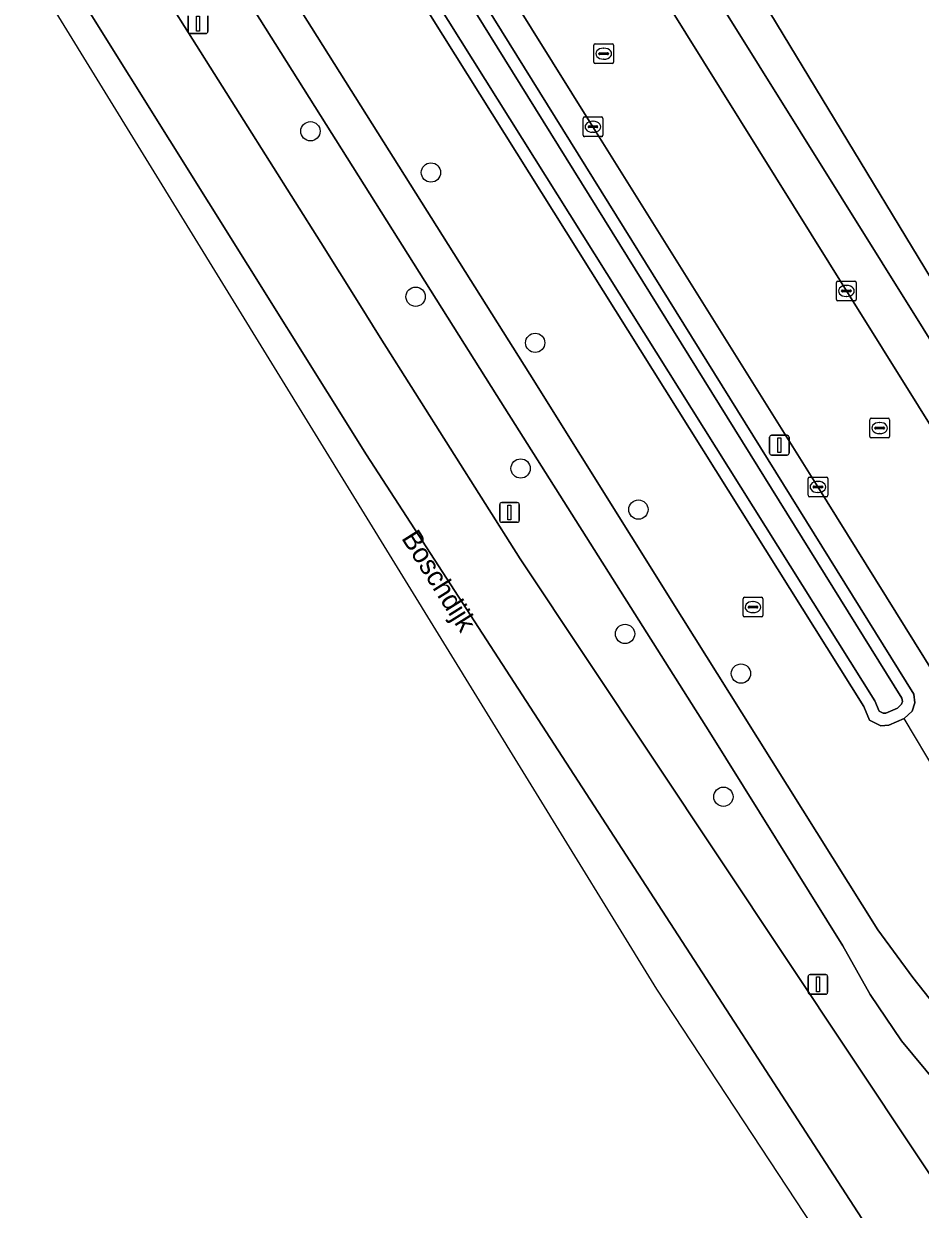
# Model space of a CAD drawing. Extents: x 158835 to 160077, y 386387 to 387778.
# Drawn here: x 159046.4 to 159091.8, y 386814 to 386874.1 of the extents above; entities that cross this region are included whole.
import ezdxf

# ---------------------------------------------------------------- set-up
doc = ezdxf.new("R2010")
doc.units = 0
for name, color, linetype in [('IMGEO_Berm_groen', 7, 'Continuous'), ('IMGEO_Boom', 7, 'Continuous'), ('IMGEO_Brandkraan', 7, 'Continuous'), ('IMGEO_Duiker', 7, 'Continuous'), ('IMGEO_Fietspad_gesloten', 7, 'Continuous'), ('IMGEO_Greppel_droge_sloot', 7, 'Continuous'), ('IMGEO_Kolk', 7, 'Continuous'), ('IMGEO_Lichtmast', 7, 'Continuous'), ('IMGEO_Loofbos', 7, 'Continuous'), ('IMGEO_Oever', 7, 'Continuous'), ('IMGEO_Openbare_ruimte_label', 7, 'Continuous'), ('IMGEO_Rijbaan_lokaal_open', 7, 'Continuous'), ('IMGEO_Rijbaan_regionaal_gesloten', 7, 'Continuous'), ('IMGEO_Rioolput', 7, 'Continuous'), ('IMGEO_Voetpad_open', 7, 'Continuous')]:
    doc.layers.add(name, color=color, linetype=linetype)

msp = doc.modelspace()

# ---------------------------------------------------------------- linework, layer by layer
at = {"layer": 'IMGEO_Berm_groen'}
for points in [[(159035.265, 386925.216), (159000, 386981.943), (158990.004, 386998.024), (158991.693, 386999.224), (159000, 386986.242), (159057.921, 386894.086), (159063.62, 386885.019), (159091.508, 386840.108), (159091.568, 386839.665), (159091.422, 386839.242), (159091.028, 386838.871), (159090.244, 386838.524), (159089.835, 386838.498), (159089.256, 386838.78), (159088.981, 386839.474), (159055.682, 386892.626)], [(159142.528, 386822.4), (159123.048, 386814.194), (159109.025, 386833.71), (159070.867, 386896.72), (159089.158, 386908.868)]]:
    msp.add_lwpolyline(points, close=True, dxfattribs=at)
for points in [[(159096.401, 386906.705), (159091.296, 386914.922), (159067.709, 386900.255), (159067.552, 386900.158), (159076.413, 386885.966), (159075.363, 386885.31), (159125.228, 386805.37)], [(159051.929, 386888.316), (159072.053, 386856.336), (159079.753, 386844.002), (159082.8, 386839.159), (159089.683, 386828.15), (159091.461, 386825.74), (159093.442, 386823.227), (159095.249, 386821.212), (159101.304, 386815.324), (159102.451, 386814.209), (159102.504, 386814.154), (159105.291, 386810.988), (159107.784, 386807.586), (159123.016, 386783.333), (159143.952, 386750)], [(159101.834, 386811.269), (159099.079, 386814.018), (159096.324, 386816.766), (159093.62, 386819.341), (159092.687, 386820.335), (159090.889, 386822.524), (159089.294, 386824.866), (159087.914, 386827.34), (159081.168, 386838.156), (159070.38, 386855.242), (159050.784, 386886.396)], [(159048.457, 386883.647), (159061.455, 386863.013), (159063.391, 386859.93), (159064.463, 386858.196), (159071.557, 386846.971), (159095.09, 386811.591)], [(159128.6, 386783.846), (159121.784, 386794.465), (159121.337, 386794.968), (159120.937, 386795.51), (159119.183, 386798.375), (159108.33, 386815.791), (159097.471, 386833.198), (159086.653, 386850.613), (159075.251, 386868.876), (159065.997, 386883.711)]]:
    msp.add_lwpolyline(points, dxfattribs=at)
at = {"layer": 'IMGEO_Boom'}
for centre in [(159060.934, 386868.651), (159067.04, 386866.557), (159066.264, 386860.259), (159072.323, 386857.92), (159071.586, 386851.549), (159077.553, 386849.464), (159076.875, 386843.159), (159082.751, 386841.147), (159081.861, 386834.9)]:
    msp.add_circle(centre, 0.489, dxfattribs=at)
at = {"layer": 'IMGEO_Brandkraan'}
for p, q in [((159082.859, 386844.091), (159082.859, 386844.943)), ((159082.934, 386845.017), (159083.786, 386845.017)), ((159083.118, 386844.511), (159083.118, 386844.523)), ((159083.556, 386844.474), (159083.158, 386844.474)), ((159083.161, 386844.56), (159083.559, 386844.56)), ((159083.347, 386844.797), (159083.372, 386844.797)), ((159083.602, 386844.523), (159083.602, 386844.511)), ((159083.86, 386844.943), (159083.86, 386844.091)), ((159083.786, 386844.017), (159082.934, 386844.017)), ((159083.37, 386844.237), (159083.345, 386844.237))]:
    msp.add_line(p, q, dxfattribs=at)
for points in [[(159082.859, 386844.091), (159082.859, 386844.943)], [(159082.934, 386845.017), (159083.786, 386845.017)], [(159083.86, 386844.943), (159083.86, 386844.091)], [(159083.786, 386844.017), (159082.934, 386844.017)]]:
    msp.add_lwpolyline(points, dxfattribs=at)
for centre, radius, start, end in [((159082.936, 386844.941), 0.0765, 91.55205, 178.44795), ((159082.936, 386844.941), 0.0765, 91.55205, 178.44795), ((159083.158, 386844.52), 0.0403, 85.87752, 175.75265), ((159083.155, 386844.51), 0.0366, 178.93798, 274.71019), ((159083.559, 386844.517), 0.043, 264.86636, 352.45326), ((159083.563, 386844.522), 0.0386, 1.73085, 96.63898), ((159083.784, 386844.941), 0.0765, 1.55205, 88.44795), ((159083.784, 386844.941), 0.0765, 1.55205, 88.44795), ((159082.936, 386844.093), 0.0765, 181.55205, 268.44795), ((159082.936, 386844.093), 0.0765, 181.55205, 268.44795), ((159083.784, 386844.093), 0.0765, 271.55205, 358.44795), ((159083.784, 386844.093), 0.0765, 271.55205, 358.44795)]:
    msp.add_arc(centre, radius, start, end, dxfattribs=at)
for centre, major_axis, ratio, start_param, end_param in [((159083.346, 386844.517), (-0.387, 0.002), 0.722429, 4.712389, 7.853982), ((159083.371, 386844.517), (-0.39, 0.002), 0.717154, 1.570796, 4.712389)]:
    msp.add_ellipse(centre, major_axis=major_axis, ratio=ratio, start_param=start_param, end_param=end_param, dxfattribs=at)
at = {"layer": 'IMGEO_Duiker'}
msp.add_lwpolyline([(159092.842, 386835.807), (159092.695, 386836.055), (159091.028, 386838.871)], dxfattribs=at)
at = {"layer": 'IMGEO_Fietspad_gesloten'}
for points in [[(159143.952, 386750), (159123.016, 386783.333), (159107.784, 386807.586), (159105.291, 386810.988), (159102.504, 386814.154), (159102.451, 386814.209), (159101.304, 386815.324), (159095.249, 386821.212), (159093.442, 386823.227), (159091.461, 386825.74), (159089.683, 386828.15), (159082.8, 386839.159), (159079.753, 386844.002), (159072.053, 386856.336), (159051.929, 386888.316)], [(159050.784, 386886.396), (159070.38, 386855.242), (159081.168, 386838.156), (159087.914, 386827.34), (159089.294, 386824.866), (159090.889, 386822.524), (159092.687, 386820.335), (159093.62, 386819.341), (159096.324, 386816.766), (159099.079, 386814.018), (159101.834, 386811.269), (159102.217, 386810.854), (159103.824, 386808.91), (159105.251, 386806.829), (159117.605, 386787.425), (159119.088, 386785.097), (159120.445, 386782.966), (159121.265, 386781.617), (159125.349, 386775.064), (159128.77, 386769.613)]]:
    msp.add_lwpolyline(points, dxfattribs=at)
at = {"layer": 'IMGEO_Greppel_droge_sloot'}
msp.add_lwpolyline([(158999.473, 386985.908), (158991.52, 386998.336), (158991.091, 386998.031), (158990.844, 386997.855), (159000.53, 386982.272), (159035.794, 386925.546), (159056.211, 386892.957), (159089.54, 386839.757), (159089.747, 386839.235), (159089.96, 386839.131), (159090.093, 386839.14), (159090.678, 386839.399), (159090.882, 386839.591), (159090.93, 386839.728), (159090.907, 386839.892), (159063.091, 386884.688), (159057.393, 386893.754)], close=True, dxfattribs=at)
at = {"layer": 'IMGEO_Kolk'}
for p, q in [((159074.749, 386868.45), (159074.749, 386869.302)), ((159074.824, 386869.376), (159075.676, 386869.376)), ((159075.237, 386869.156), (159075.262, 386869.156)), ((159075.75, 386869.302), (159075.75, 386868.45)), ((159075.008, 386868.87), (159075.008, 386868.882)), ((159075.446, 386868.833), (159075.048, 386868.833)), ((159075.051, 386868.919), (159075.449, 386868.919)), ((159075.26, 386868.596), (159075.235, 386868.596)), ((159075.492, 386868.882), (159075.492, 386868.87)), ((159075.676, 386868.376), (159074.824, 386868.376)), ((159087.592, 386860.125), (159087.592, 386860.977)), ((159087.667, 386861.051), (159088.519, 386861.051)), ((159088.08, 386860.831), (159088.105, 386860.831)), ((159088.593, 386860.977), (159088.593, 386860.125)), ((159087.851, 386860.545), (159087.851, 386860.557)), ((159088.289, 386860.508), (159087.891, 386860.508)), ((159087.894, 386860.594), (159088.292, 386860.594)), ((159088.103, 386860.271), (159088.078, 386860.271)), ((159088.335, 386860.557), (159088.335, 386860.545)), ((159088.519, 386860.051), (159087.667, 386860.051)), ((159086.225, 386851.113), (159087.077, 386851.113)), ((159086.15, 386850.187), (159086.15, 386851.039)), ((159086.409, 386850.607), (159086.409, 386850.619)), ((159086.847, 386850.57), (159086.449, 386850.57)), ((159086.452, 386850.656), (159086.85, 386850.656)), ((159086.638, 386850.893), (159086.663, 386850.893)), ((159086.893, 386850.619), (159086.893, 386850.607)), ((159087.151, 386851.039), (159087.151, 386850.187)), ((159087.077, 386850.113), (159086.225, 386850.113)), ((159086.661, 386850.333), (159086.636, 386850.333))]:
    msp.add_line(p, q, dxfattribs=at)
for points in [[(159074.749, 386868.45), (159074.749, 386869.302)], [(159074.824, 386869.376), (159075.676, 386869.376)], [(159075.75, 386869.302), (159075.75, 386868.45)], [(159075.676, 386868.376), (159074.824, 386868.376)], [(159087.592, 386860.125), (159087.592, 386860.977)], [(159087.667, 386861.051), (159088.519, 386861.051)], [(159088.593, 386860.977), (159088.593, 386860.125)], [(159088.519, 386860.051), (159087.667, 386860.051)], [(159086.225, 386851.113), (159087.077, 386851.113)], [(159086.15, 386850.187), (159086.15, 386851.039)], [(159087.151, 386851.039), (159087.151, 386850.187)], [(159087.077, 386850.113), (159086.225, 386850.113)]]:
    msp.add_lwpolyline(points, dxfattribs=at)
for centre, radius, start, end in [((159074.826, 386869.3), 0.0765, 91.55205, 178.44795), ((159074.826, 386869.3), 0.0765, 91.55205, 178.44795), ((159075.674, 386869.3), 0.0765, 1.55205, 88.44795), ((159075.674, 386869.3), 0.0765, 1.55205, 88.44795), ((159075.048, 386868.879), 0.0403, 85.87752, 175.75265), ((159075.045, 386868.869), 0.0366, 178.93798, 274.71019), ((159075.449, 386868.876), 0.043, 264.86636, 352.45326), ((159075.453, 386868.881), 0.0386, 1.73085, 96.63898), ((159074.826, 386868.452), 0.0765, 181.55205, 268.44795), ((159074.826, 386868.452), 0.0765, 181.55205, 268.44795), ((159075.674, 386868.452), 0.0765, 271.55205, 358.44795), ((159075.674, 386868.452), 0.0765, 271.55205, 358.44795), ((159087.669, 386860.975), 0.0765, 91.55205, 178.44795), ((159087.669, 386860.975), 0.0765, 91.55205, 178.44795), ((159088.517, 386860.975), 0.0765, 1.55205, 88.44795), ((159088.517, 386860.975), 0.0765, 1.55205, 88.44795), ((159087.669, 386860.127), 0.0765, 181.55205, 268.44795), ((159087.669, 386860.127), 0.0765, 181.55205, 268.44795), ((159087.891, 386860.554), 0.0403, 85.87752, 175.75265), ((159087.888, 386860.544), 0.0366, 178.93798, 274.71019), ((159088.292, 386860.551), 0.043, 264.86636, 352.45326), ((159088.296, 386860.556), 0.0386, 1.73085, 96.63898), ((159088.517, 386860.127), 0.0765, 271.55205, 358.44795), ((159088.517, 386860.127), 0.0765, 271.55205, 358.44795), ((159086.227, 386851.037), 0.0765, 91.55205, 178.44795), ((159086.227, 386851.037), 0.0765, 91.55205, 178.44795), ((159087.075, 386851.037), 0.0765, 1.55205, 88.44795), ((159087.075, 386851.037), 0.0765, 1.55205, 88.44795), ((159086.449, 386850.616), 0.0403, 85.87752, 175.75265), ((159086.446, 386850.606), 0.0366, 178.93798, 274.71019), ((159086.85, 386850.613), 0.043, 264.86636, 352.45326), ((159086.854, 386850.618), 0.0386, 1.73085, 96.63898), ((159086.227, 386850.189), 0.0765, 181.55205, 268.44795), ((159086.227, 386850.189), 0.0765, 181.55205, 268.44795), ((159087.075, 386850.189), 0.0765, 271.55205, 358.44795), ((159087.075, 386850.189), 0.0765, 271.55205, 358.44795)]:
    msp.add_arc(centre, radius, start, end, dxfattribs=at)
for centre, major_axis, ratio, start_param, end_param in [((159075.236, 386868.876), (-0.387, 0.002), 0.722429, 4.712389, 7.853982), ((159075.261, 386868.876), (-0.39, 0.002), 0.717154, 1.570796, 4.712389), ((159088.079, 386860.551), (-0.387, 0.002), 0.722429, 4.712389, 7.853982), ((159088.104, 386860.551), (-0.39, 0.002), 0.717154, 1.570796, 4.712389), ((159086.637, 386850.613), (-0.387, 0.002), 0.722429, 4.712389, 7.853982), ((159086.662, 386850.613), (-0.39, 0.002), 0.717154, 1.570796, 4.712389)]:
    msp.add_ellipse(centre, major_axis=major_axis, ratio=ratio, start_param=start_param, end_param=end_param, dxfattribs=at)
at = {"layer": 'IMGEO_Lichtmast'}
for p, q in [((159054.746, 386873.707), (159054.746, 386874.507)), ((159054.746, 386874.507), (159054.746, 386873.707)), ((159055.736, 386874.507), (159055.736, 386873.707)), ((159055.736, 386873.707), (159055.736, 386874.507)), ((159055.636, 386873.607), (159054.846, 386873.607)), ((159054.846, 386873.607), (159055.636, 386873.607)), ((159084.198, 386852.331), (159084.198, 386853.131)), ((159084.198, 386853.131), (159084.198, 386852.331)), ((159084.298, 386853.231), (159085.088, 386853.231)), ((159085.088, 386853.231), (159084.298, 386853.231)), ((159085.188, 386853.131), (159085.188, 386852.331)), ((159085.188, 386852.331), (159085.188, 386853.131)), ((159085.088, 386852.231), (159084.298, 386852.231)), ((159084.298, 386852.231), (159085.088, 386852.231)), ((159070.525, 386848.918), (159070.525, 386849.718)), ((159070.525, 386849.718), (159070.525, 386848.918)), ((159070.625, 386849.818), (159071.415, 386849.818)), ((159071.415, 386849.818), (159070.625, 386849.818)), ((159071.515, 386849.718), (159071.515, 386848.918)), ((159071.515, 386848.918), (159071.515, 386849.718)), ((159071.415, 386848.818), (159070.625, 386848.818)), ((159070.625, 386848.818), (159071.415, 386848.818)), ((159086.253, 386825.885), (159087.043, 386825.885)), ((159087.043, 386825.885), (159086.253, 386825.885)), ((159086.153, 386824.985), (159086.153, 386825.785)), ((159086.153, 386825.785), (159086.153, 386824.985)), ((159087.143, 386825.785), (159087.143, 386824.985)), ((159087.143, 386824.985), (159087.143, 386825.785)), ((159087.043, 386824.885), (159086.253, 386824.885)), ((159086.253, 386824.885), (159087.043, 386824.885))]:
    msp.add_line(p, q, dxfattribs=at)
for points in [[(159055.166, 386874.482), (159055.316, 386874.482), (159055.316, 386873.732), (159055.166, 386873.732), (159055.166, 386874.482)], [(159084.618, 386853.106), (159084.768, 386853.106), (159084.768, 386852.356), (159084.618, 386852.356), (159084.618, 386853.106)], [(159070.945, 386849.693), (159071.095, 386849.693), (159071.095, 386848.943), (159070.945, 386848.943), (159070.945, 386849.693)], [(159086.573, 386825.76), (159086.723, 386825.76), (159086.723, 386825.01), (159086.573, 386825.01), (159086.573, 386825.76)]]:
    msp.add_lwpolyline(points, dxfattribs=at)
for centre, start, end in [((159054.846, 386873.707), 180, 270), ((159054.846, 386873.707), 180, 270), ((159055.636, 386873.707), 270, 0), ((159055.636, 386873.707), 270, 0), ((159084.298, 386853.131), 90, 180), ((159084.298, 386853.131), 90, 180), ((159085.088, 386853.131), 0, 90), ((159085.088, 386853.131), 360, 90), ((159084.298, 386852.331), 180, 270), ((159084.298, 386852.331), 180, 270), ((159085.088, 386852.331), 270, 0), ((159085.088, 386852.331), 270, 0), ((159070.625, 386849.718), 90, 180), ((159070.625, 386849.718), 90, 180), ((159071.415, 386849.718), 0, 90), ((159071.415, 386849.718), 360, 90), ((159070.625, 386848.918), 180, 270), ((159070.625, 386848.918), 180, 270), ((159071.415, 386848.918), 270, 0), ((159071.415, 386848.918), 270, 0), ((159086.253, 386825.785), 90, 180), ((159086.253, 386825.785), 90, 180), ((159087.043, 386825.785), 0, 90), ((159087.043, 386825.785), 360, 90), ((159086.253, 386824.985), 180, 270), ((159086.253, 386824.985), 180, 270), ((159087.043, 386824.985), 270, 0), ((159087.043, 386824.985), 270, 0)]:
    msp.add_arc(centre, 0.1, start, end, dxfattribs=at)
at = {"layer": 'IMGEO_Loofbos'}
msp.add_lwpolyline([(159123.048, 386814.194), (159142.528, 386822.4), (159089.158, 386908.868), (159070.867, 386896.72), (159109.025, 386833.71)], close=True, dxfattribs=at)
at = {"layer": 'IMGEO_Oever'}
for points in [[(159000, 386986.242), (158991.693, 386999.224), (158990.004, 386998.024), (159000, 386981.943), (159035.265, 386925.216), (159055.682, 386892.626), (159088.981, 386839.474), (159089.256, 386838.78), (159089.835, 386838.498), (159090.244, 386838.524), (159091.028, 386838.871), (159091.422, 386839.242), (159091.568, 386839.665), (159091.508, 386840.108), (159063.62, 386885.019), (159057.921, 386894.086)], [(158999.473, 386985.908), (159057.393, 386893.754), (159063.091, 386884.688), (159090.907, 386839.892), (159090.93, 386839.728), (159090.882, 386839.591), (159090.678, 386839.399), (159090.093, 386839.14), (159089.96, 386839.131), (159089.747, 386839.235), (159089.54, 386839.757), (159056.211, 386892.957), (159035.794, 386925.546), (159000.53, 386982.272), (158990.844, 386997.855), (158991.091, 386998.031), (158991.52, 386998.336)]]:
    msp.add_lwpolyline(points, close=True, dxfattribs=at)
at = {"layer": 'IMGEO_Rijbaan_lokaal_open'}
for points in [[(159065.997, 386883.711), (159075.251, 386868.876), (159086.653, 386850.613), (159097.471, 386833.198), (159108.33, 386815.791), (159119.183, 386798.375), (159120.937, 386795.51), (159121.337, 386794.968), (159121.784, 386794.465), (159122.274, 386794.003), (159122.804, 386793.587), (159123.173, 386793.339), (159124.451, 386792.618), (159125.788, 386792.014), (159127.174, 386791.531), (159128.597, 386791.175), (159129.11, 386791.079), (159129.323, 386791.054), (159129.442, 386791.04)], [(159123.327, 386804.096), (159120.096, 386809.226), (159109.823, 386825.714), (159098.952, 386843.149), (159088.091, 386860.551), (159077.264, 386877.959)]]:
    msp.add_lwpolyline(points, dxfattribs=at)
at = {"layer": 'IMGEO_Rijbaan_regionaal_gesloten'}
msp.add_lwpolyline([(158852.084, 387188.493), (158892.201, 387121.78), (158943.79, 387040.765), (159022.005, 386917.023), (159078.47, 386825.145), (159142.367, 386727.985), (159143.031, 386728.393), (159114.787, 386773.529), (159063.769, 386852.239), (159047.794, 386877.825), (159027.337, 386910.591), (159001.844, 386951.425), (158973.435, 386996.928), (158951.308, 387032.368), (158919.283, 387083.664), (158891.623, 387127.967), (158871.393, 387160.012), (158853.231, 387189.196)], close=True, dxfattribs=at)
msp.add_lwpolyline([(159047.794, 386877.825), (159063.769, 386852.239), (159114.787, 386773.529), (159143.031, 386728.393), (159146.173, 386730.325), (159146.161, 386730.344), (159145.513, 386731.372), (159137.834, 386743.694), (159134, 386749.851), (159098.75, 386806.078), (159095.71, 386810.659), (159095.09, 386811.591), (159071.557, 386846.971), (159064.463, 386858.196), (159063.391, 386859.93), (159061.455, 386863.013), (159048.457, 386883.647)], dxfattribs=at)
at = {"layer": 'IMGEO_Rioolput'}
for p, q in [((159075.294, 386872.158), (159075.294, 386873.01)), ((159075.369, 386873.084), (159076.221, 386873.084)), ((159075.782, 386872.864), (159075.807, 386872.864)), ((159076.295, 386873.01), (159076.295, 386872.158)), ((159075.553, 386872.578), (159075.553, 386872.59)), ((159075.991, 386872.541), (159075.593, 386872.541)), ((159075.596, 386872.627), (159075.994, 386872.627)), ((159075.805, 386872.304), (159075.78, 386872.304)), ((159076.037, 386872.59), (159076.037, 386872.578)), ((159076.221, 386872.084), (159075.369, 386872.084)), ((159089.353, 386854.097), (159090.205, 386854.097)), ((159089.278, 386853.171), (159089.278, 386854.023)), ((159089.537, 386853.591), (159089.537, 386853.603)), ((159089.975, 386853.554), (159089.577, 386853.554)), ((159089.58, 386853.64), (159089.978, 386853.64)), ((159089.766, 386853.877), (159089.791, 386853.877)), ((159090.021, 386853.603), (159090.021, 386853.591)), ((159090.279, 386854.023), (159090.279, 386853.171)), ((159090.205, 386853.097), (159089.353, 386853.097)), ((159089.789, 386853.317), (159089.764, 386853.317))]:
    msp.add_line(p, q, dxfattribs=at)
for points in [[(159075.294, 386872.158), (159075.294, 386873.01)], [(159075.369, 386873.084), (159076.221, 386873.084)], [(159076.295, 386873.01), (159076.295, 386872.158)], [(159076.221, 386872.084), (159075.369, 386872.084)], [(159089.353, 386854.097), (159090.205, 386854.097)], [(159089.278, 386853.171), (159089.278, 386854.023)], [(159090.279, 386854.023), (159090.279, 386853.171)], [(159090.205, 386853.097), (159089.353, 386853.097)]]:
    msp.add_lwpolyline(points, dxfattribs=at)
for centre, radius, start, end in [((159075.371, 386873.008), 0.0765, 91.55205, 178.44795), ((159075.371, 386873.008), 0.0765, 91.55205, 178.44795), ((159076.219, 386873.008), 0.0765, 1.55205, 88.44795), ((159076.219, 386873.008), 0.0765, 1.55205, 88.44795), ((159075.371, 386872.16), 0.0765, 181.55205, 268.44795), ((159075.371, 386872.16), 0.0765, 181.55205, 268.44795), ((159075.593, 386872.587), 0.0403, 85.87752, 175.75265), ((159075.59, 386872.577), 0.0366, 178.93798, 274.71019), ((159075.994, 386872.584), 0.043, 264.86636, 352.45326), ((159075.998, 386872.589), 0.0386, 1.73085, 96.63898), ((159076.219, 386872.16), 0.0765, 271.55205, 358.44795), ((159076.219, 386872.16), 0.0765, 271.55205, 358.44795), ((159089.355, 386854.021), 0.0765, 91.55205, 178.44795), ((159089.355, 386854.021), 0.0765, 91.55205, 178.44795), ((159090.203, 386854.021), 0.0765, 1.55205, 88.44795), ((159090.203, 386854.021), 0.0765, 1.55205, 88.44795), ((159089.577, 386853.6), 0.0403, 85.87752, 175.75265), ((159089.574, 386853.59), 0.0366, 178.93798, 274.71019), ((159089.978, 386853.597), 0.043, 264.86636, 352.45326), ((159089.982, 386853.602), 0.0386, 1.73085, 96.63898), ((159089.355, 386853.173), 0.0765, 181.55205, 268.44795), ((159089.355, 386853.173), 0.0765, 181.55205, 268.44795), ((159090.203, 386853.173), 0.0765, 271.55205, 358.44795), ((159090.203, 386853.173), 0.0765, 271.55205, 358.44795)]:
    msp.add_arc(centre, radius, start, end, dxfattribs=at)
for centre, major_axis, ratio, start_param, end_param in [((159075.781, 386872.584), (-0.387, 0.002), 0.722429, 4.712389, 7.853982), ((159075.806, 386872.584), (-0.39, 0.002), 0.717154, 1.570796, 4.712389), ((159089.765, 386853.597), (-0.387, 0.002), 0.722429, 4.712389, 7.853982), ((159089.79, 386853.597), (-0.39, 0.002), 0.717154, 1.570796, 4.712389)]:
    msp.add_ellipse(centre, major_axis=major_axis, ratio=ratio, start_param=start_param, end_param=end_param, dxfattribs=at)
at = {"layer": 'IMGEO_Voetpad_open'}
for points in [[(159125.228, 386805.37), (159075.363, 386885.31), (159076.413, 386885.966), (159067.552, 386900.158), (159066.88, 386899.741), (159066.666, 386899.609), (159066.583, 386899.738), (159064.514, 386898.388), (159065.265, 386897.218)], [(159073.44, 386884.112), (159077.264, 386877.959), (159088.091, 386860.551), (159098.952, 386843.149), (159109.823, 386825.714), (159120.096, 386809.226), (159123.327, 386804.096)]]:
    msp.add_lwpolyline(points, dxfattribs=at)

# ---------------------------------------------------------------- texts
at = {"layer": 'IMGEO_Openbare_ruimte_label'}
msp.add_text('Boschdijk', height=1, rotation=302.05394, dxfattribs=at).set_placement((159065.517, 386848.018))

doc.saveas('drawing.dxf')
